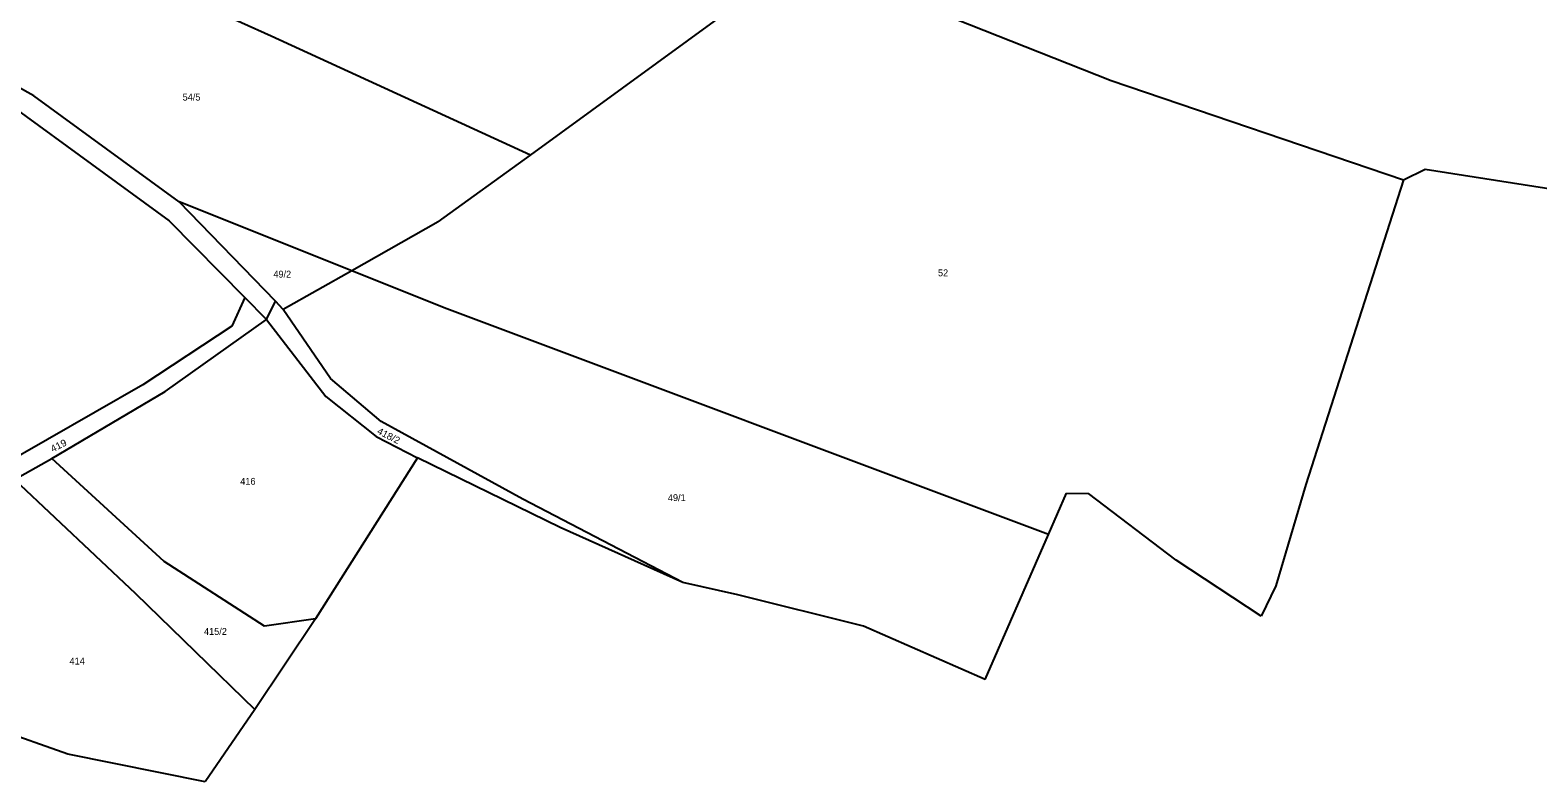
# Model space of a CAD drawing. Extents: x -791548 to -789311, y -1142631 to -1140855.
# Drawn here: x -790140.3 to -789765.7, y -1142561.3 to -1142374.6 of the extents above; entities that cross this region are included whole.
import ezdxf
from ezdxf.enums import TextEntityAlignment as Align

# ---------------------------------------------------------------- set-up
doc = ezdxf.new("R2010")
doc.units = 0
doc.header["$LTSCALE"] = 0.68
doc.layers.add('1', color=7, linetype='Continuous', lineweight=25)
doc.layers.add('2', color=7, linetype='Continuous')

msp = doc.modelspace()

# ---------------------------------------------------------------- linework, layer by layer
at = {"layer": '1'}
for p, q in [((-790080.46, -1142376.06), (-790146.61, -1142346.2)), ((-790016.01, -1142405.65), (-789948.68, -1142356.55)), ((-789948.68, -1142356.55), (-789871.73, -1142387.1)), ((-790016.01, -1142405.65), (-790080.46, -1142376.06)), ((-790139.43, -1142390.88), (-790157.14, -1142381.01)), ((-789871.73, -1142387.1), (-789799.07, -1142411.7)), ((-790103.32, -1142417.18), (-790139.43, -1142390.88)), ((-790144.43, -1142393.74), (-790105.81, -1142421.92)), ((-790038.97, -1142422.16), (-790016.01, -1142405.65)), ((-789799.07, -1142411.7), (-789793.65, -1142409.1)), ((-789793.65, -1142409.1), (-789746.89, -1142416.4)), ((-789799.07, -1142411.7), (-789823.32, -1142487.4)), ((-790060.42, -1142434.31), (-790103.32, -1142417.18)), ((-790079.41, -1142441.91), (-790103.32, -1142417.18)), ((-790105.81, -1142421.92), (-790087.01, -1142441)), ((-790038.97, -1142422.16), (-790060.42, -1142434.31)), ((-790060.42, -1142434.31), (-790077.43, -1142443.95)), ((-790037.42, -1142443.5), (-790060.42, -1142434.31)), ((-790087.01, -1142441), (-790090.23, -1142448.07)), ((-790081.58, -1142446.41), (-790087.01, -1142441)), ((-790081.58, -1142446.41), (-790079.41, -1142441.91)), ((-790077.43, -1142443.95), (-790079.41, -1142441.91)), ((-790065.73, -1142461.11), (-790077.43, -1142443.95)), ((-789887.27, -1142499.87), (-790037.42, -1142443.5)), ((-790106.76, -1142464.29), (-790081.58, -1142446.41)), ((-790081.58, -1142446.41), (-790066.85, -1142465.57)), ((-790090.23, -1142448.07), (-790112.31, -1142462.65)), ((-790112.31, -1142462.65), (-790147.93, -1142483.02)), ((-790053.07, -1142471.78), (-790065.73, -1142461.11)), ((-790134.99, -1142480.92), (-790106.76, -1142464.29)), ((-790066.85, -1142465.57), (-790054.35, -1142475.5)), ((-790017.89, -1142491.08), (-790053.07, -1142471.78)), ((-790054.35, -1142475.5), (-790044.08, -1142480.78)), ((-790144.19, -1142486.18), (-790134.99, -1142480.92)), ((-790107.07, -1142506.5), (-790134.99, -1142480.92)), ((-790044.08, -1142480.78), (-790069.42, -1142520.8)), ((-790008.63, -1142498.08), (-790044.08, -1142480.78)), ((-790144.19, -1142486.18), (-790114.15, -1142514.52)), ((-789823.32, -1142487.4), (-789830.77, -1142512.55)), ((-789978.18, -1142511.78), (-790017.89, -1142491.08)), ((-789887.27, -1142499.87), (-789882.79, -1142489.6)), ((-789882.79, -1142489.6), (-789877.31, -1142489.67)), ((-789855.58, -1142506.21), (-789877.31, -1142489.67)), ((-789978.18, -1142511.78), (-790008.63, -1142498.08)), ((-789903, -1142535.89), (-789887.27, -1142499.87)), ((-790082.1, -1142522.57), (-790107.07, -1142506.5)), ((-789834.43, -1142520.08), (-789855.58, -1142506.21)), ((-790114.15, -1142514.52), (-790084.5, -1142543.31)), ((-789964.51, -1142514.8), (-789978.18, -1142511.78)), ((-789933.28, -1142522.63), (-789964.51, -1142514.8)), ((-789830.77, -1142512.55), (-789834.43, -1142520.08)), ((-790069.42, -1142520.8), (-790084.5, -1142543.31)), ((-790069.42, -1142520.8), (-790082.1, -1142522.57)), ((-789903, -1142535.89), (-789933.28, -1142522.63)), ((-790130.99, -1142554.38), (-790163.09, -1142543.11)), ((-790084.5, -1142543.31), (-790096.83, -1142561.27)), ((-790096.83, -1142561.27), (-790130.99, -1142554.38))]:
    msp.add_line(p, q, dxfattribs=at)

# ---------------------------------------------------------------- texts
at = {"layer": '2'}
for s, p in [('54/5', (-790100.239, -1142392.052)), ('49/2', (-790077.689, -1142436.022)), ('52', (-789913.469, -1142435.692)), ('416', (-790086.229, -1142487.472)), ('49/1', (-789979.649, -1142491.532)), ('415/2', (-790094.3, -1142524.772)), ('414', (-790128.659, -1142532.132))]:
    msp.add_text(s, height=1.7, dxfattribs=at).set_placement(p, align=Align.CENTER)
for s, rotation, width, p in [('418/2', 333, 1.05, (-790051.6259, -1142476.0625)), ('419', 27, 1.1, (-790132.8909, -1142478.5125))]:
    msp.add_text(s, height=1.7, rotation=rotation, dxfattribs=dict(at, width=width)).set_placement(p, align=Align.CENTER)

doc.saveas('drawing.dxf')
